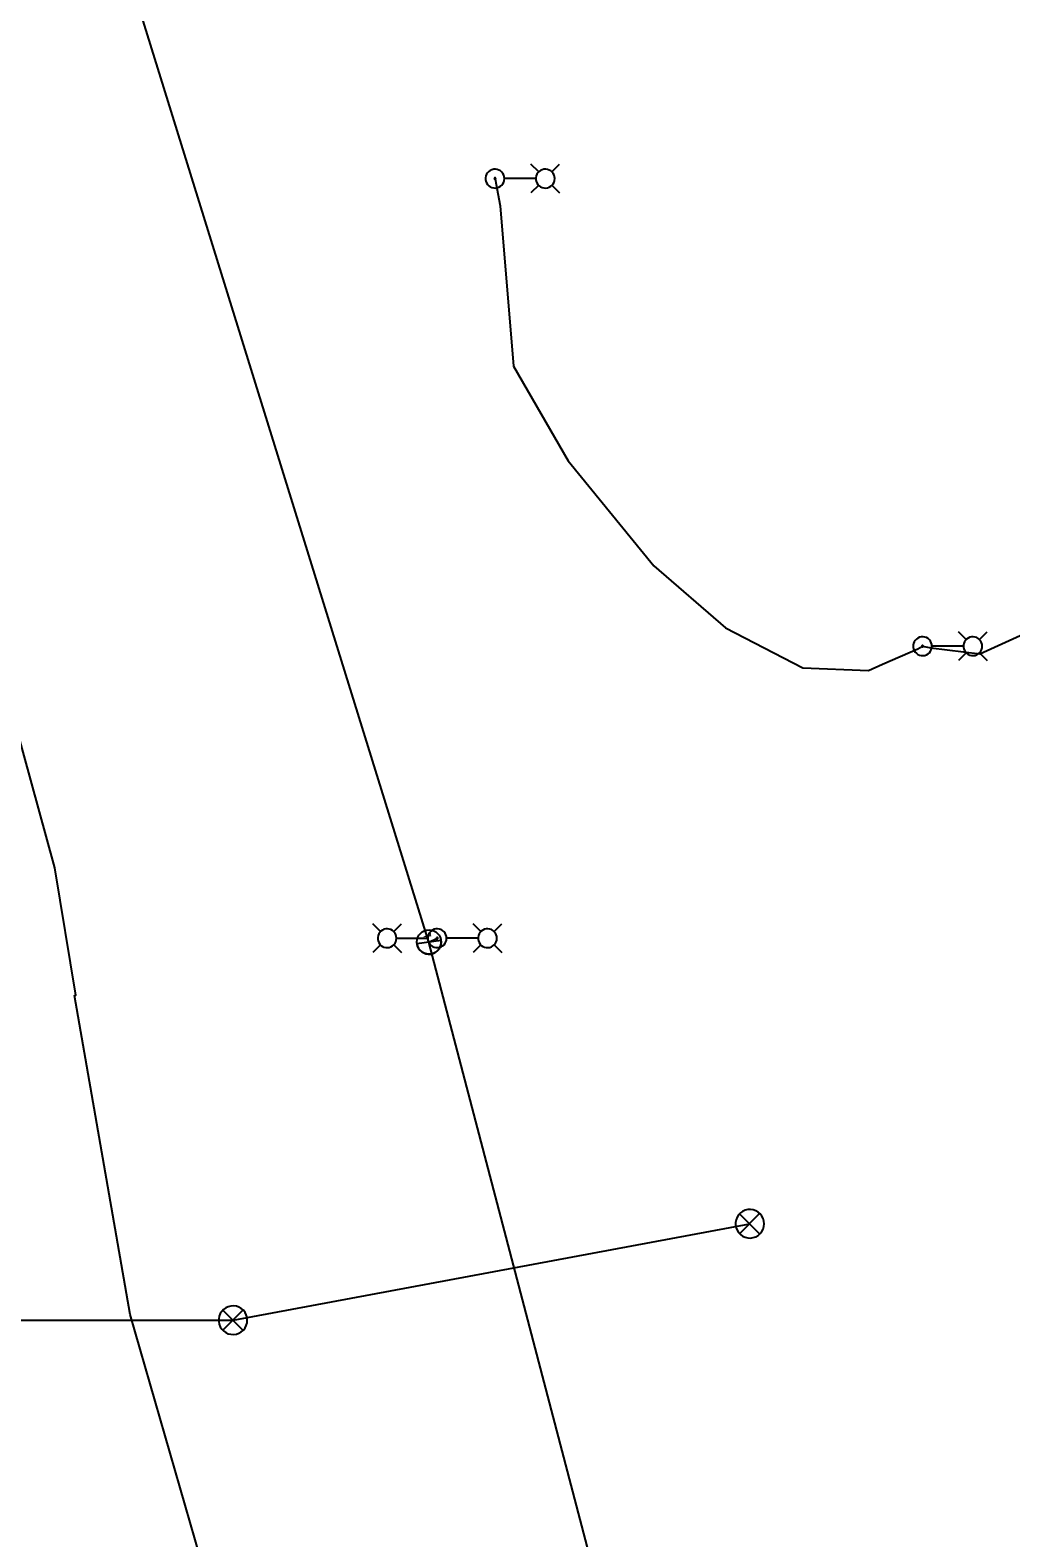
# Model space of a CAD drawing. Extents: x 596028 to 606371, y 330010 to 403088.
# Drawn here: x 604033 to 604259.3, y 349225.3 to 349573.3 of the extents above; entities that cross this region are included whole.
import ezdxf

# ---------------------------------------------------------------- set-up
doc = ezdxf.new("R2010")
doc.units = 0
for name, color, linetype in [('E_FTMS', 7, 'Continuous'), ('E_FTMS_Conduit', 7, 'Continuous'), ('E_LTG', 7, 'Continuous'), ('E_LTG_CID', 7, 'Continuous')]:
    doc.layers.add(name, color=color, linetype=linetype)

# ---------------------------------------------------------------- blocks, each defined once
blk = doc.blocks.new('_U272')
at = {"layer": 'E_LTG'}
blk.add_lwpolyline([(0.001, -0.171), (0.001, 0.172)], dxfattribs=at)
blk.add_circle((0.001, 0), 0.171, dxfattribs=at)
blk.add_arc((0.001, 0), 0.171, 90, 270, dxfattribs=at)
blk.add_text('L', height=0.108, dxfattribs=at).set_placement((0.066, -0.042))

msp = doc.modelspace()

# ---------------------------------------------------------------- linework, layer by layer
at = {"layer": 'E_FTMS'}
for points in [[(604202.34, 349297.83), (604202.28, 349298.45), (604202.1, 349299.06), (604201.82, 349299.61), (604201.43, 349300.11), (604200.95, 349300.52), (604200.41, 349300.83), (604199.82, 349301.04), (604199.2, 349301.12), (604198.57, 349301.1), (604197.96, 349300.95), (604197.39, 349300.69), (604196.88, 349300.32), (604196.45, 349299.87), (604196.11, 349299.34), (604195.87, 349298.76), (604195.75, 349298.14), (604195.75, 349297.51), (604195.87, 349296.9), (604196.11, 349296.32), (604196.45, 349295.79), (604196.88, 349295.33), (604197.39, 349294.97), (604197.96, 349294.71), (604198.57, 349294.56), (604199.2, 349294.53), (604199.82, 349294.62), (604200.41, 349294.83), (604200.95, 349295.14), (604201.43, 349295.55), (604201.82, 349296.04), (604202.1, 349296.6), (604202.28, 349297.2), (604202.34, 349297.83)], [(604201.3, 349300.16), (604196.69, 349295.51)], [(604196.69, 349300.12), (604201.34, 349295.46)], [(604083.08, 349275.57), (604083.02, 349276.2), (604082.85, 349276.8), (604082.56, 349277.36), (604082.17, 349277.85), (604081.7, 349278.26), (604081.15, 349278.58), (604080.56, 349278.78), (604079.94, 349278.87), (604079.31, 349278.84), (604078.7, 349278.69), (604078.13, 349278.43), (604077.62, 349278.07), (604077.19, 349277.61), (604076.85, 349277.09), (604076.62, 349276.5), (604076.5, 349275.89), (604076.5, 349275.26), (604076.62, 349274.64), (604076.85, 349274.06), (604077.19, 349273.53), (604077.62, 349273.08), (604078.13, 349272.72), (604078.7, 349272.46), (604079.31, 349272.31), (604079.94, 349272.28), (604080.56, 349272.37), (604081.15, 349272.57), (604081.7, 349272.89), (604082.17, 349273.3), (604082.56, 349273.79), (604082.85, 349274.35), (604083.02, 349274.95), (604083.08, 349275.57)], [(604082.04, 349277.91), (604077.43, 349273.25)], [(604077.43, 349277.86), (604082.09, 349273.21)]]:
    msp.add_lwpolyline(points, dxfattribs=at)
at = {"layer": 'E_FTMS_Conduit'}
for points in [[(604122.74, 348988.04), (604108.56, 349049.67), (604100.88, 349081.84), (604090.92, 349138.93), (604079.09, 349196.91), (604056.03, 349276.86), (604043.16, 349350.52), (604043.52, 349350.57), (604038.65, 349379.99), (604027.8, 349419.58), (604014.43, 349447.39), (603999.06, 349483.4), (603987.98, 349514.15), (603982.63, 349526.67)], [(603899.78, 349275.57), (604079.78, 349275.57), (604199.04, 349297.83)]]:
    msp.add_lwpolyline(points, dxfattribs=at)
at = {"layer": 'E_LTG'}
for points in [[(604150.33, 349540.57), (604148.55, 349542.34)], [(604153.38, 349540.57), (604155.15, 349542.34)], [(604142.42, 349539.04), (604142.38, 349539.45), (604142.27, 349539.85), (604142.08, 349540.22), (604141.82, 349540.54), (604141.51, 349540.82), (604141.15, 349541.02), (604140.76, 349541.16), (604140.35, 349541.22), (604139.94, 349541.2), (604139.54, 349541.1), (604139.16, 349540.93), (604138.82, 349540.69), (604138.54, 349540.39), (604138.31, 349540.04), (604138.16, 349539.66), (604138.08, 349539.25), (604138.08, 349538.84), (604138.16, 349538.43), (604138.31, 349538.05), (604138.54, 349537.7), (604138.82, 349537.4), (604139.16, 349537.16), (604139.54, 349536.99), (604139.94, 349536.89), (604140.35, 349536.87), (604140.76, 349536.93), (604141.15, 349537.06), (604141.51, 349537.27), (604141.82, 349537.54), (604142.08, 349537.87), (604142.27, 349538.23), (604142.38, 349538.63), (604142.42, 349539.04)], [(604140.41, 349539.04), (604140.41, 349539.07), (604140.4, 349539.1), (604140.39, 349539.13), (604140.37, 349539.16), (604140.34, 349539.18), (604140.32, 349539.19), (604140.29, 349539.2), (604140.26, 349539.21), (604140.22, 349539.21), (604140.19, 349539.2), (604140.16, 349539.19), (604140.14, 349539.17), (604140.12, 349539.15), (604140.1, 349539.12), (604140.09, 349539.09), (604140.08, 349539.06), (604140.08, 349539.03), (604140.09, 349539), (604140.1, 349538.97), (604140.12, 349538.94), (604140.14, 349538.92), (604140.16, 349538.9), (604140.19, 349538.89), (604140.22, 349538.88), (604140.26, 349538.88), (604140.29, 349538.88), (604140.32, 349538.89), (604140.34, 349538.91), (604140.37, 349538.93), (604140.39, 349538.95), (604140.4, 349538.98), (604140.41, 349539.01), (604140.41, 349539.04)], [(604149.64, 349539.04), (604142.46, 349539.04)], [(604154.03, 349539.04), (604153.99, 349539.45), (604153.87, 349539.85), (604153.68, 349540.22), (604153.43, 349540.54), (604153.11, 349540.82), (604152.75, 349541.02), (604152.36, 349541.16), (604151.95, 349541.22), (604151.54, 349541.2), (604151.14, 349541.1), (604150.76, 349540.93), (604150.43, 349540.69), (604150.14, 349540.39), (604149.92, 349540.04), (604149.76, 349539.66), (604149.69, 349539.25), (604149.69, 349538.84), (604149.76, 349538.43), (604149.92, 349538.05), (604150.14, 349537.7), (604150.43, 349537.4), (604150.76, 349537.16), (604151.14, 349536.99), (604151.54, 349536.89), (604151.95, 349536.87), (604152.36, 349536.93), (604152.75, 349537.06), (604153.11, 349537.27), (604153.43, 349537.54), (604153.68, 349537.87), (604153.87, 349538.23), (604153.99, 349538.63), (604154.03, 349539.04)], [(604150.33, 349537.52), (604148.55, 349535.74)], [(604153.38, 349537.52), (604155.15, 349535.74)], [(604249, 349432.65), (604247.22, 349434.42)], [(604252.04, 349432.65), (604253.82, 349434.42)], [(604241.09, 349431.12), (604241.05, 349431.53), (604240.93, 349431.93), (604240.74, 349432.3), (604240.49, 349432.62), (604240.18, 349432.89), (604239.82, 349433.1), (604239.43, 349433.24), (604239.02, 349433.3), (604238.6, 349433.28), (604238.2, 349433.18), (604237.83, 349433.01), (604237.49, 349432.77), (604237.2, 349432.47), (604236.98, 349432.12), (604236.83, 349431.74), (604236.75, 349431.33), (604236.75, 349430.92), (604236.83, 349430.51), (604236.98, 349430.13), (604237.2, 349429.78), (604237.49, 349429.48), (604237.83, 349429.24), (604238.2, 349429.07), (604238.6, 349428.97), (604239.02, 349428.95), (604239.43, 349429.01), (604239.82, 349429.14), (604240.18, 349429.35), (604240.49, 349429.62), (604240.74, 349429.95), (604240.93, 349430.31), (604241.05, 349430.71), (604241.09, 349431.12)], [(604239.08, 349431.12), (604239.08, 349431.15), (604239.07, 349431.18), (604239.05, 349431.21), (604239.03, 349431.24), (604239.01, 349431.26), (604238.98, 349431.27), (604238.95, 349431.28), (604238.92, 349431.29), (604238.89, 349431.29), (604238.86, 349431.28), (604238.83, 349431.27), (604238.81, 349431.25), (604238.78, 349431.22), (604238.77, 349431.2), (604238.75, 349431.17), (604238.75, 349431.14), (604238.75, 349431.11), (604238.75, 349431.08), (604238.77, 349431.05), (604238.78, 349431.02), (604238.81, 349431), (604238.83, 349430.98), (604238.86, 349430.96), (604238.89, 349430.96), (604238.92, 349430.96), (604238.95, 349430.96), (604238.98, 349430.97), (604239.01, 349430.99), (604239.03, 349431.01), (604239.05, 349431.03), (604239.07, 349431.06), (604239.08, 349431.09), (604239.08, 349431.12)], [(604248.31, 349431.12), (604241.13, 349431.12)], [(604252.69, 349431.12), (604252.65, 349431.53), (604252.54, 349431.93), (604252.35, 349432.3), (604252.09, 349432.62), (604251.78, 349432.89), (604251.42, 349433.1), (604251.03, 349433.24), (604250.62, 349433.3), (604250.21, 349433.28), (604249.81, 349433.18), (604249.43, 349433.01), (604249.09, 349432.77), (604248.81, 349432.47), (604248.58, 349432.12), (604248.43, 349431.74), (604248.35, 349431.33), (604248.35, 349430.92), (604248.43, 349430.51), (604248.58, 349430.13), (604248.81, 349429.78), (604249.09, 349429.48), (604249.43, 349429.24), (604249.81, 349429.07), (604250.21, 349428.97), (604250.62, 349428.95), (604251.03, 349429.01), (604251.42, 349429.14), (604251.78, 349429.35), (604252.09, 349429.62), (604252.35, 349429.95), (604252.54, 349430.31), (604252.65, 349430.71), (604252.69, 349431.12)], [(604249, 349429.6), (604247.22, 349427.82)], [(604252.04, 349429.6), (604253.82, 349427.82)], [(604113.81, 349365.25), (604112.03, 349367.03)], [(604117.51, 349363.73), (604117.47, 349364.14), (604117.35, 349364.54), (604117.17, 349364.9), (604116.91, 349365.23), (604116.6, 349365.5), (604116.24, 349365.71), (604115.85, 349365.84), (604115.44, 349365.9), (604115.03, 349365.88), (604114.62, 349365.78), (604114.25, 349365.61), (604113.91, 349365.37), (604113.63, 349365.07), (604113.4, 349364.72), (604113.25, 349364.34), (604113.17, 349363.93), (604113.17, 349363.52), (604113.25, 349363.11), (604113.4, 349362.73), (604113.63, 349362.38), (604113.91, 349362.08), (604114.25, 349361.84), (604114.62, 349361.67), (604115.03, 349361.57), (604115.44, 349361.55), (604115.85, 349361.61), (604116.24, 349361.75), (604116.6, 349361.95), (604116.91, 349362.23), (604117.17, 349362.55), (604117.35, 349362.92), (604117.47, 349363.31), (604117.51, 349363.73)], [(604116.86, 349365.25), (604118.63, 349367.03)], [(604129.08, 349363.73), (604129.04, 349364.14), (604128.92, 349364.53), (604128.73, 349364.9), (604128.48, 349365.23), (604128.16, 349365.5), (604127.8, 349365.71), (604127.41, 349365.84), (604127, 349365.9), (604126.59, 349365.88), (604126.19, 349365.78), (604125.81, 349365.61), (604125.48, 349365.37), (604125.19, 349365.07), (604124.97, 349364.72), (604124.81, 349364.34), (604124.74, 349363.93), (604124.74, 349363.52), (604124.81, 349363.11), (604124.97, 349362.73), (604125.19, 349362.38), (604125.48, 349362.08), (604125.81, 349361.84), (604126.19, 349361.67), (604126.59, 349361.57), (604127, 349361.55), (604127.41, 349361.61), (604127.8, 349361.75), (604128.16, 349361.95), (604128.48, 349362.22), (604128.73, 349362.55), (604128.92, 349362.92), (604129.04, 349363.31), (604129.08, 349363.73)], [(604136.98, 349365.25), (604135.2, 349367.03)], [(604140.68, 349363.73), (604140.64, 349364.14), (604140.52, 349364.53), (604140.33, 349364.9), (604140.08, 349365.23), (604139.77, 349365.5), (604139.41, 349365.71), (604139.02, 349365.84), (604138.61, 349365.9), (604138.19, 349365.88), (604137.79, 349365.78), (604137.42, 349365.61), (604137.08, 349365.37), (604136.79, 349365.07), (604136.57, 349364.72), (604136.42, 349364.34), (604136.34, 349363.93), (604136.34, 349363.52), (604136.42, 349363.11), (604136.57, 349362.73), (604136.79, 349362.38), (604137.08, 349362.08), (604137.42, 349361.84), (604137.79, 349361.67), (604138.19, 349361.57), (604138.61, 349361.55), (604139.02, 349361.61), (604139.41, 349361.75), (604139.77, 349361.95), (604140.08, 349362.22), (604140.33, 349362.55), (604140.52, 349362.92), (604140.64, 349363.31), (604140.68, 349363.73)], [(604140.03, 349365.25), (604141.8, 349367.03)], [(604113.81, 349362.2), (604112.03, 349360.43)], [(604116.86, 349362.2), (604118.63, 349360.43)], [(604117.55, 349363.73), (604124.73, 349363.73)], [(604127.07, 349363.73), (604127.06, 349363.76), (604127.06, 349363.79), (604127.04, 349363.82), (604127.02, 349363.84), (604127, 349363.86), (604126.97, 349363.88), (604126.94, 349363.89), (604126.91, 349363.89), (604126.88, 349363.89), (604126.85, 349363.88), (604126.82, 349363.87), (604126.79, 349363.85), (604126.77, 349363.83), (604126.75, 349363.8), (604126.74, 349363.77), (604126.74, 349363.74), (604126.74, 349363.71), (604126.74, 349363.68), (604126.75, 349363.65), (604126.77, 349363.62), (604126.79, 349363.6), (604126.82, 349363.58), (604126.85, 349363.57), (604126.88, 349363.56), (604126.91, 349363.56), (604126.94, 349363.56), (604126.97, 349363.57), (604127, 349363.59), (604127.02, 349363.61), (604127.04, 349363.64), (604127.06, 349363.66), (604127.06, 349363.69), (604127.07, 349363.73)], [(604136.29, 349363.73), (604129.11, 349363.73)], [(604136.98, 349362.2), (604135.2, 349360.43)], [(604140.03, 349362.2), (604141.8, 349360.43)]]:
    msp.add_lwpolyline(points, dxfattribs=at)
at = {"layer": 'E_LTG_CID'}
for points in [[(604318.05, 348339.7), (604287.36, 348606.91), (604242.16, 348872.6), (604188.57, 349120.13), (604125.01, 349362.84), (604050.82, 349602.08), (604014.23, 349708.06), (603966.43, 349837.54), (603869.82, 350091.09), (603838.85, 350172.22), (603784.41, 350315.72), (603699.29, 350539.43), (603613.87, 350764.2), (603510.34, 351036.54), (603442.84, 351213.06), (603357.76, 351436.96)], [(604140.26, 349539.04), (604140.44, 349538.05), (604141.42, 349532.73), (604144.51, 349495.79), (604157.14, 349473.94), (604176.87, 349449.66), (604193.45, 349435.35), (604211.28, 349426.13), (604226.42, 349425.48), (604229.66, 349426.98), (604237.82, 349430.49), (604238.91, 349431.12), (604240.8, 349430.71), (604252.17, 349429.36), (604273.46, 349439.04), (604289.87, 349449.39), (604295.59, 349452.78), (604301.99, 349455.29), (604331.14, 349473.25)], [(604125.01, 349362.84), (604126.9, 349363.73)]]:
    msp.add_lwpolyline(points, dxfattribs=at)

# ---------------------------------------------------------------- block references
at = {"layer": 'E_LTG_CID', "xscale": 16.404166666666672, "yscale": 16.404166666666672, "rotation": 97.82095686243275}
msp.add_blockref('_U272', (604125.02, 349362.83), dxfattribs=at)

doc.saveas('drawing.dxf')
